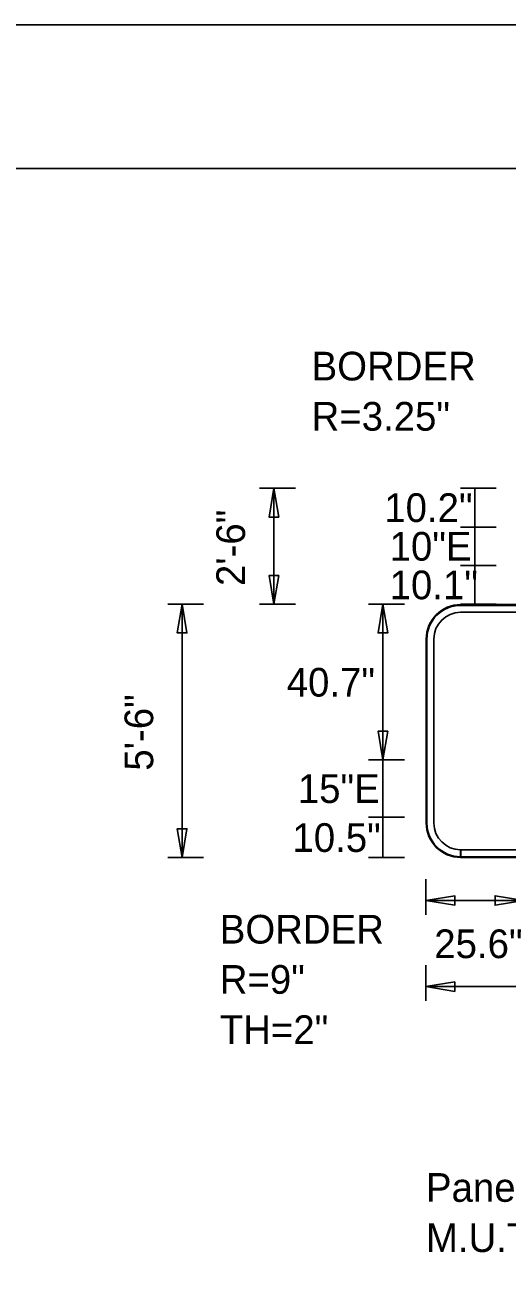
# Model space of a CAD drawing. Extents: x 1806251 to 1809821, y 414895 to 422886.
# Drawn here: x 1809675.736 to 1809676.996, y 415080.964 to 415084.226 of the extents above; entities that cross this region are included whole.
import ezdxf

# ---------------------------------------------------------------- set-up
doc = ezdxf.new("R2010")
doc.units = 0
for name, color, linetype in [('GSBWFILL', 7, 'Continuous'), ('GSCOLORFILL', 7, 'Continuous'), ('GSDIMS', 7, 'Continuous'), ('GSOUTLINE', 7, 'Continuous'), ('GSSHT', 7, 'Continuous')]:
    doc.layers.add(name, color=color, linetype=linetype)

msp = doc.modelspace()

# ---------------------------------------------------------------- linework, layer by layer
at = {"layer": 'GSBWFILL'}
for p, q in [((1809678.3156, 415082.7111), (1809676.8746, 415082.7111)), ((1809676.8746, 415082.6911), (1809678.3156, 415082.6911)), ((1809676.7846, 415082.6211), (1809676.7846, 415082.1401)), ((1809676.8046, 415082.1401), (1809676.8046, 415082.6211)), ((1809676.8746, 415082.0501), (1809676.8746, 415082.0701)), ((1809678.3156, 415082.0701), (1809676.8748, 415082.0701)), ((1809676.8748, 415082.0701), (1809676.8748, 415082.0501)), ((1809676.8748, 415082.0501), (1809678.3156, 415082.0501))]:
    msp.add_line(p, q, dxfattribs=at)
for centre, radius, start, end in [((1809676.8746, 415082.6211), 0.09, 90, 180), ((1809676.8746, 415082.6211), 0.07, 90, 180), ((1809676.8746, 415082.1401), 0.09, 180, 270), ((1809676.8746, 415082.1401), 0.07, 180, 270)]:
    msp.add_arc(centre, radius, start, end, dxfattribs=at)
at = {"layer": 'GSCOLORFILL'}
for p, q in [((1809678.3156, 415082.7111), (1809676.8746, 415082.7111)), ((1809678.3156, 415082.7111), (1809676.8746, 415082.7111)), ((1809678.3156, 415082.7111), (1809676.8746, 415082.7111)), ((1809676.8746, 415082.7091), (1809678.3156, 415082.7091)), ((1809676.8746, 415082.6911), (1809678.3156, 415082.6911)), ((1809676.7846, 415082.6211), (1809676.7846, 415082.1401)), ((1809676.7846, 415082.6211), (1809676.7846, 415082.1401)), ((1809676.7846, 415082.6211), (1809676.7846, 415082.1401)), ((1809676.7866, 415082.1401), (1809676.7866, 415082.6211)), ((1809676.8046, 415082.1401), (1809676.8046, 415082.6211)), ((1809676.8746, 415082.0501), (1809676.8746, 415082.0701)), ((1809678.3156, 415082.0701), (1809676.8748, 415082.0701)), ((1809676.8748, 415082.0701), (1809676.8748, 415082.0501)), ((1809676.8746, 415082.0501), (1809676.8746, 415082.0521)), ((1809678.3156, 415082.0521), (1809676.8746, 415082.0521)), ((1809676.8746, 415082.0521), (1809676.8746, 415082.0501)), ((1809676.8746, 415082.0501), (1809678.3156, 415082.0501)), ((1809676.8746, 415082.0501), (1809678.3156, 415082.0501)), ((1809676.8748, 415082.0501), (1809678.3156, 415082.0501))]:
    msp.add_line(p, q, dxfattribs=at)
for centre, radius, start, end in [((1809676.8746, 415082.6211), 0.09, 90, 180), ((1809676.8746, 415082.6211), 0.09, 90, 180), ((1809676.8746, 415082.6211), 0.09, 90, 180), ((1809676.8746, 415082.6211), 0.088, 90, 180), ((1809676.8746, 415082.6211), 0.07, 90, 180), ((1809676.8746, 415082.1401), 0.09, 180, 270), ((1809676.8746, 415082.1401), 0.09, 180, 270), ((1809676.8746, 415082.1401), 0.09, 180, 270), ((1809676.8746, 415082.1401), 0.088, 180, 270), ((1809676.8746, 415082.1401), 0.07, 180, 270)]:
    msp.add_arc(centre, radius, start, end, dxfattribs=at)
at = {"layer": 'GSDIMS'}
for p, q in [((1809676.4427, 415083.015), (1809676.349, 415083.015)), ((1809676.3865, 415082.712), (1809676.3865, 415083.015)), ((1809676.9678, 415083.015), (1809676.874, 415083.015)), ((1809676.9115, 415082.9135), (1809676.9115, 415083.015)), ((1809676.9678, 415082.9135), (1809676.874, 415082.9135)), ((1809676.9678, 415082.9135), (1809676.874, 415082.9135)), ((1809676.9115, 415082.9135), (1809676.9115, 415082.8135)), ((1809676.9678, 415082.8135), (1809676.874, 415082.8135)), ((1809676.9678, 415082.8135), (1809676.874, 415082.8135)), ((1809676.9115, 415082.712), (1809676.9115, 415082.8135)), ((1809676.2027, 415082.712), (1809676.109, 415082.712)), ((1809676.1465, 415082.05), (1809676.1465, 415082.712)), ((1809676.4427, 415082.712), (1809676.349, 415082.712)), ((1809676.7278, 415082.712), (1809676.634, 415082.712)), ((1809676.6715, 415082.3051), (1809676.6715, 415082.712)), ((1809676.9678, 415082.712), (1809676.874, 415082.712)), ((1809676.7278, 415082.3051), (1809676.634, 415082.3051)), ((1809676.7278, 415082.3051), (1809676.634, 415082.3051)), ((1809676.6715, 415082.3051), (1809676.6715, 415082.1551)), ((1809676.7278, 415082.1551), (1809676.634, 415082.1551)), ((1809676.7278, 415082.1551), (1809676.634, 415082.1551)), ((1809676.6715, 415082.05), (1809676.6715, 415082.1551)), ((1809676.2027, 415082.05), (1809676.109, 415082.05)), ((1809676.7278, 415082.05), (1809676.634, 415082.05)), ((1809676.784, 415081.9938), (1809676.784, 415081.9)), ((1809676.784, 415081.9375), (1809677.0397, 415081.9375)), ((1809676.784, 415081.7688), (1809676.784, 415081.675)), ((1809676.784, 415081.7125), (1809678.406, 415081.7125))]:
    msp.add_line(p, q, dxfattribs=at)
for points in [[(1809676.3865, 415083.015), (1809676.399, 415082.94), (1809676.374, 415082.94)], [(1809676.3865, 415082.712), (1809676.399, 415082.787), (1809676.374, 415082.787)], [(1809676.1465, 415082.712), (1809676.159, 415082.637), (1809676.134, 415082.637)], [(1809676.6715, 415082.712), (1809676.684, 415082.637), (1809676.659, 415082.637)], [(1809676.6715, 415082.3051), (1809676.684, 415082.3801), (1809676.659, 415082.3801)], [(1809676.1465, 415082.05), (1809676.159, 415082.125), (1809676.134, 415082.125)], [(1809676.784, 415081.9375), (1809676.859, 415081.95), (1809676.859, 415081.925)], [(1809677.0397, 415081.9375), (1809676.9647, 415081.95), (1809676.9647, 415081.925)], [(1809676.784, 415081.7125), (1809676.859, 415081.725), (1809676.859, 415081.7)]]:
    msp.add_lwpolyline(points, close=True, dxfattribs=at)
at = {"layer": 'GSOUTLINE'}
for p, q in [((1809678.3156, 415082.7111), (1809676.8746, 415082.7111)), ((1809678.3156, 415082.6911), (1809676.8746, 415082.6911)), ((1809676.7846, 415082.6211), (1809676.7846, 415082.1401)), ((1809676.8046, 415082.6211), (1809676.8046, 415082.1401)), ((1809676.8746, 415082.0701), (1809678.3156, 415082.0701)), ((1809676.8746, 415082.0501), (1809678.3156, 415082.0501))]:
    msp.add_line(p, q, dxfattribs=at)
for centre, radius, start, end in [((1809676.8746, 415082.6211), 0.09, 90, 180), ((1809676.8746, 415082.6211), 0.07, 90, 180), ((1809676.8746, 415082.1401), 0.09, 180, 270), ((1809676.8746, 415082.1401), 0.07, 180, 270)]:
    msp.add_arc(centre, radius, start, end, dxfattribs=at)
at = {"layer": 'GSSHT'}
msp.add_line((1809672.1349, 415084.2262), (1809684.8891, 415084.2262), dxfattribs=at)
msp.add_lwpolyline([(1809672.634, 415083.8512), (1809684.6381, 415083.8512), (1809684.6381, 415076.3475), (1809672.634, 415076.3475)], close=True, dxfattribs=at)

# ---------------------------------------------------------------- texts
at = {"layer": 'GSDIMS'}
for s, p in [('BORDER', (1809676.485, 415083.297)), ('R=3.25"', (1809676.485, 415083.1658)), ('10.2"', (1809676.675, 415082.927)), ('10"E', (1809676.689, 415082.826)), ('10.1"', (1809676.689, 415082.725)), ('40.7"', (1809676.42, 415082.4706)), ('15"E', (1809676.449, 415082.1926)), ('10.5"', (1809676.435, 415082.0646)), ('BORDER', (1809676.245, 415081.825)), ('25.6"', (1809676.8057, 415081.787)), ('R=9"', (1809676.245, 415081.6938)), ('TH=2"', (1809676.245, 415081.5625)), ('Panel Style: guide_fwy_overhead.ssi', (1809676.784, 415081.15)), ('M.U.T.C.D.: 2009 Edition', (1809676.784, 415081.0188))]:
    msp.add_text(s, height=0.075, dxfattribs=at).set_placement(p)
for s, p in [('2\'-6"', (1809676.311, 415082.7595)), ('5\'-6"', (1809676.071, 415082.277))]:
    msp.add_text(s, height=0.075, rotation=90, dxfattribs=at).set_placement(p)

doc.saveas('drawing.dxf')
